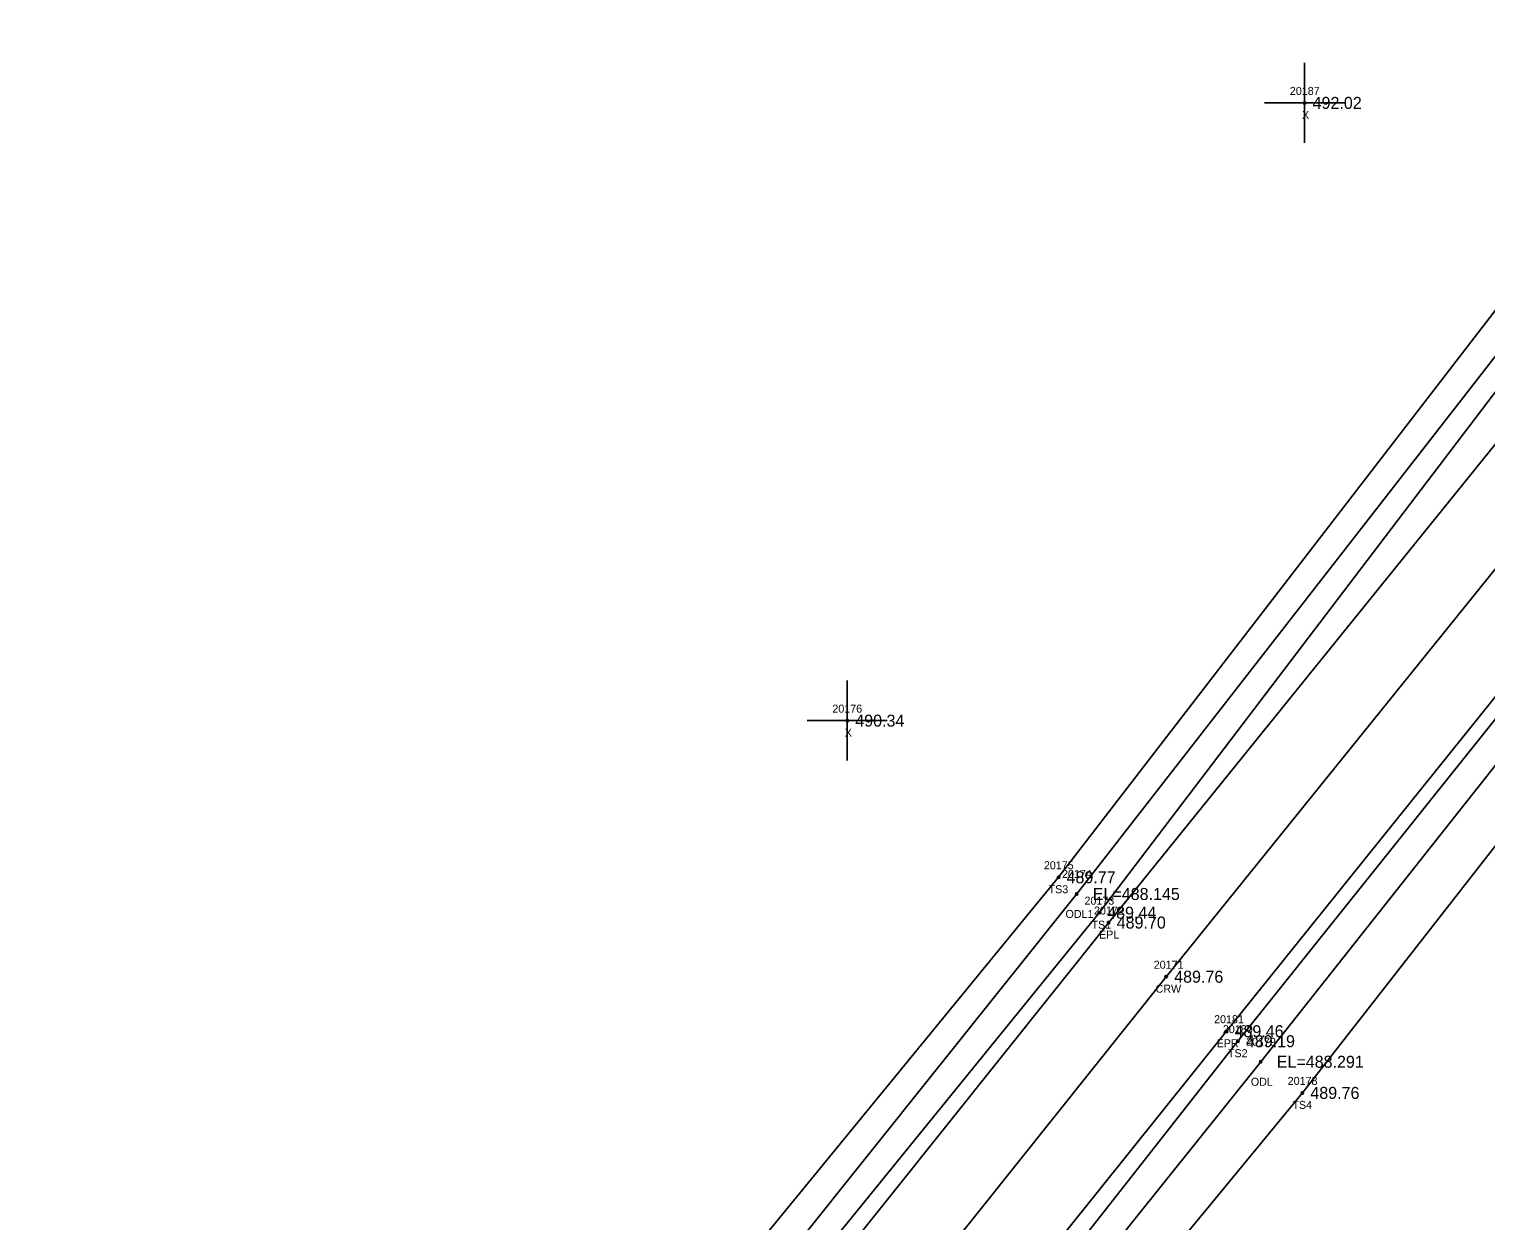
# Model space of a CAD drawing. Extents: x 1789565 to 1790548, y 909019 to 910194.
# Drawn here: x 1790172.5 to 1790354.5, y 909900.3 to 910049.2 of the extents above; entities that cross this region are included whole.
import ezdxf

# ---------------------------------------------------------------- set-up
doc = ezdxf.new("R2010")
doc.units = 0
for name, color, linetype in [('RD_DTM_BkLn1', 7, 'Continuous'), ('RD_DTM_BkLn2', 7, 'Continuous'), ('RD_DTM_BkLn_txCode', 7, 'Continuous'), ('RD_EX_H2O', 7, 'Continuous'), ('RD_EX_H2O_txCode', 7, 'Continuous'), ('RD_EX_Misc', 7, 'Continuous'), ('RD_EX_Misc_txCode', 7, 'Continuous'), ('RD_EX_Road', 7, 'Continuous'), ('RD_EX_Road_txCode', 7, 'Continuous'), ('RD_EX_TX_H2O_ELEV', 7, 'Continuous'), ('RD_EX_TX_Misc_ELEV', 7, 'Continuous'), ('RD_EX_TX_Road_ELEV', 7, 'Continuous'), ('RD_HC_Survey_ELEV', 7, 'Continuous'), ('RD_HC_Survey_txCode', 7, 'Continuous'), ('RD_SMD_Locator', 7, 'Continuous')]:
    doc.layers.add(name, color=color, linetype=linetype)

msp = doc.modelspace()

# ---------------------------------------------------------------- linework, layer by layer
at = {"layer": 'RD_DTM_BkLn1'}
msp.add_lwpolyline([(1790071.24, 909625.67), (1790132.78, 909702.56), (1790193.17, 909778.64), (1790254.11, 909855.13), (1790314.56, 909930.82), (1790375.87, 910006.79), (1790434.17, 910078.51), (1790495.95, 910153.23)], dxfattribs=at)
at = {"layer": 'RD_DTM_BkLn2'}
for points in [[(1790181.61, 909789.75), (1790181.34, 909795.67), (1790239.02, 909867.4), (1790301.11, 909943.25), (1790360.06, 910019.74), (1790418.43, 910091.45), (1790480.61, 910166.7)], [(1790060.69, 909634.71), (1790061.47, 909641.75), (1790119.6, 909713.74), (1790183.37, 909787.88), (1790244.44, 909862.78), (1790306.19, 909938.82), (1790365.07, 910016.23), (1790422.97, 910088.22), (1790484.03, 910163.43)], [(1790081.67, 909617.32), (1790086.3, 909617), (1790143.13, 909693.7), (1790202.72, 909770.52), (1790263.97, 909846.87), (1790323.52, 909922.76), (1790384.66, 909999.25), (1790423.96, 910046.28)], [(1790092.97, 909612.92), (1790097.34, 909612.95), (1790152.91, 909684.97), (1790214.4, 909761.5), (1790270.76, 909842.42), (1790331.58, 909916.3), (1790391.85, 909993.49), (1790427.85, 910042.91), (1790426.19, 910046.57), (1790423.96, 910046.28)]]:
    msp.add_lwpolyline(points, dxfattribs=at)
at = {"layer": 'RD_EX_H2O'}
for points in [[(1790181.61, 909789.75), (1790242.2, 909864.6), (1790303.39, 909941.16), (1790363.14, 910017.91), (1790421.33, 910089.83), (1790482.18, 910165.24)], [(1790092.97, 909612.92), (1790147.38, 909690.09), (1790206.86, 909767.79), (1790266.43, 909845.39), (1790326.38, 909920.19), (1790387.41, 909997.35), (1790424.69, 910044.32)]]:
    msp.add_lwpolyline(points, dxfattribs=at)
at = {"layer": 'RD_EX_Misc'}
for p, q in [((1790331.86, 910035.02), (1790331.86, 910045.02)), ((1790326.86, 910040.02), (1790336.86, 910040.02)), ((1790274.71, 909957.82), (1790274.71, 909967.82)), ((1790269.71, 909962.82), (1790279.71, 909962.82))]:
    msp.add_line(p, q, dxfattribs=at)
at = {"layer": 'RD_EX_Road'}
for points in [[(1790071.29, 909625.64), (1790063.58, 909631.76), (1790124.98, 909708.45), (1790186, 909785.5), (1790246.28, 909861.1), (1790307.38, 909937.59), (1790368.26, 910012.93), (1790426.56, 910084.73), (1790488.45, 910159.81)], [(1790071.25, 909625.72), (1790078.96, 909619.74), (1790139.76, 909696.36), (1790200.89, 909772.13), (1790261.64, 909848.6), (1790322.1, 909924.01), (1790383.38, 910000.26), (1790441.69, 910072.01), (1790503.77, 910147.05)]]:
    msp.add_lwpolyline(points, dxfattribs=at)
at = {"layer": 'RD_SMD_Locator'}
for centre in [(1790331.86, 910040.02), (1790274.71, 909962.82), (1790301.11, 909943.25), (1790303.39, 909941.16), (1790306.19, 909938.82), (1790307.38, 909937.59), (1790314.56, 909930.82), (1790322.1, 909924.01), (1790323.52, 909922.76), (1790326.38, 909920.19), (1790331.58, 909916.3)]:
    msp.add_circle(centre, 0.15, dxfattribs=at)

# ---------------------------------------------------------------- texts
at = {"layer": 'RD_DTM_BkLn_txCode'}
for s, p in [('20175', (1790299.28, 909944.25)), ('TS3', (1790299.87, 909941.25)), ('20173', (1790304.35, 909939.82)), ('TS1', (1790305.23, 909936.82)), ('20180', (1790321.65, 909923.76)), ('TS2', (1790322.28, 909920.76)), ('20178', (1790329.75, 909917.3)), ('TS4', (1790330.34, 909914.3))]:
    msp.add_text(s, height=1, dxfattribs=at).set_placement(p)
at = {"layer": 'RD_EX_H2O_txCode'}
for s, p in [('20174', (1790301.55, 909943.16)), ('ODL1', (1790301.98, 909938.16)), ('20179', (1790324.55, 909922.19)), ('ODL', (1790325.14, 909917.19))]:
    msp.add_text(s, height=1, dxfattribs=at).set_placement(p)
at = {"layer": 'RD_EX_Misc_txCode'}
for s, p in [('20187', (1790330.02, 910041.02)), ('X', (1790331.54, 910038.02)), ('20176', (1790272.85, 909963.82)), ('X', (1790274.4, 909960.82))]:
    msp.add_text(s, height=1, dxfattribs=at).set_placement(p)
at = {"layer": 'RD_EX_Road_txCode'}
for s, p in [('20172', (1790305.54, 909938.59)), ('EPL', (1790306.17, 909935.59)), ('20181', (1790320.55, 909925.01)), ('EPR', (1790320.87, 909922.01))]:
    msp.add_text(s, height=1, dxfattribs=at).set_placement(p)
at = {"layer": 'RD_EX_TX_H2O_ELEV'}
for s, p in [('EL=488.145', (1790305.39, 909940.41)), ('EL=488.291', (1790328.38, 909919.44))]:
    msp.add_text(s, height=1.5, dxfattribs=at).set_placement(p)
at = {"layer": 'RD_EX_TX_Misc_ELEV'}
for s, p in [('492.02', (1790332.86, 910039.27)), ('490.34', (1790275.71, 909962.07)), ('489.77', (1790302.11, 909942.5)), ('489.44', (1790307.19, 909938.07)), ('489.19', (1790324.52, 909922.01)), ('489.76', (1790332.58, 909915.55))]:
    msp.add_text(s, height=1.5, dxfattribs=at).set_placement(p)
at = {"layer": 'RD_EX_TX_Road_ELEV'}
for s, p in [('489.70', (1790308.38, 909936.84)), ('489.46', (1790323.1, 909923.26))]:
    msp.add_text(s, height=1.5, dxfattribs=at).set_placement(p)
at = {"layer": 'RD_HC_Survey_ELEV'}
msp.add_text('489.76', height=1.5, dxfattribs=at).set_placement((1790315.56, 909930.07))
at = {"layer": 'RD_HC_Survey_txCode'}
for s, p in [('20171', (1790313.01, 909931.82)), ('CRW', (1790313.24, 909928.82))]:
    msp.add_text(s, height=1, dxfattribs=at).set_placement(p)

doc.saveas('drawing.dxf')
